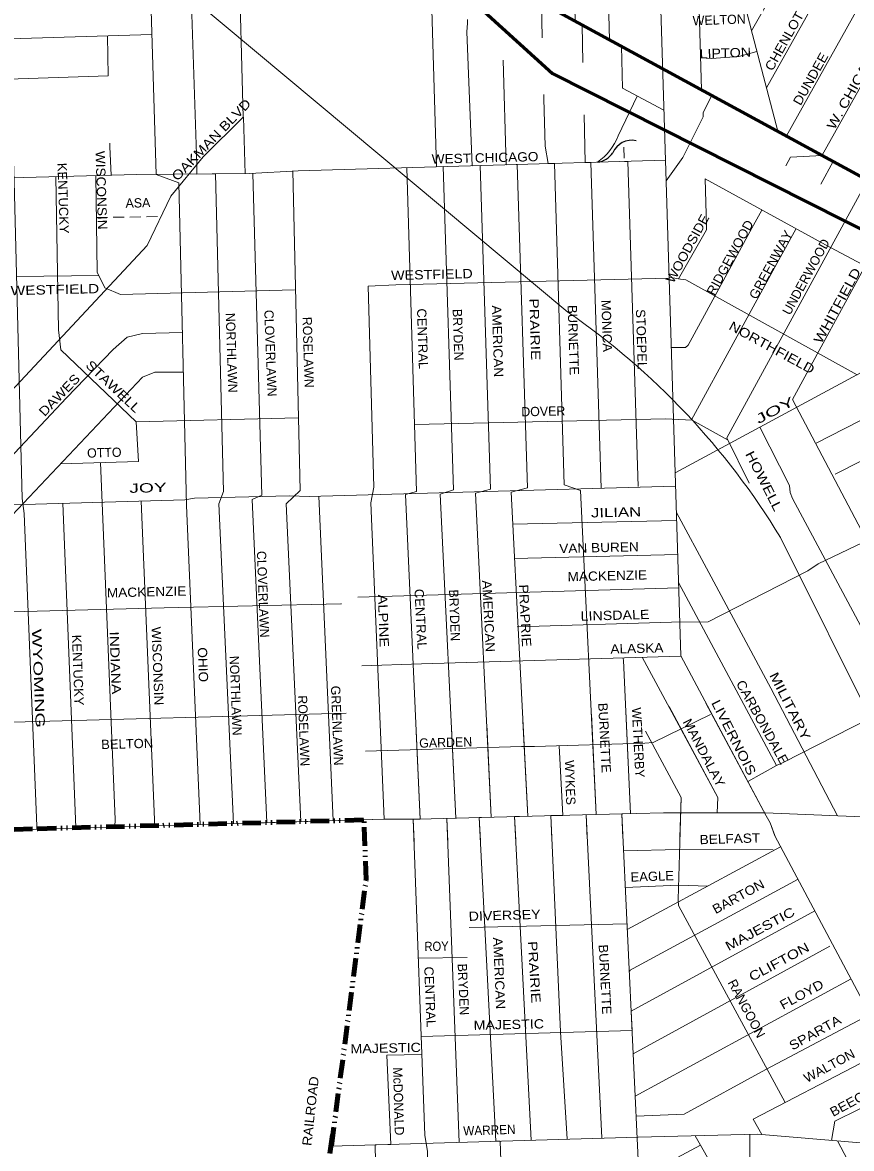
# Model space of a CAD drawing. Extents: x 34705 to 138605, y 34275 to 143551.
# Drawn here: x 69930 to 76640, y 104782 to 113900 of the extents above; entities that cross this region are included whole.
import ezdxf
from ezdxf.enums import TextEntityAlignment as Align

# ---------------------------------------------------------------- set-up
doc = ezdxf.new("R2010")
doc.units = 0
doc.header["$LTSCALE"] = 30
for name, pattern in [('DASH_DOUBLE_DOT', [9.2, 5, -1.2, 0.3, -1.2, 0.3, -1.2]), ('DOT_DASHED', [7.7, 5, -1.2, 0.3, -1.2]), ('MEDIUM_DASHED', [4.5, 3, -1.5])]:
    doc.linetypes.add(name, pattern=pattern)
for name, color, linetype, lineweight in [('1', 7, 'Continuous', 13), ('11', 7, 'Continuous', 13), ('50', 7, 'Continuous', 13), ('51', 7, 'Continuous', 35), ('59', 7, 'DASH_DOUBLE_DOT', 106), ('60', 7, 'DOT_DASHED', 53)]:
    doc.layers.add(name, color=color, linetype=linetype, lineweight=lineweight)

msp = doc.modelspace()

# ---------------------------------------------------------------- linework, layer by layer
at = {"layer": '1'}
for p, q in [((76370.24, 114795.07), (75831.64, 113831.95)), ((75391.97, 114512.52), (75425.28, 113355.5)), ((76555.08, 114450.42), (75951.76, 113371.56)), ((76740.73, 114104.26), (76113.76, 112983.11)), ((70617.43, 113793.01), (70624.07, 113468.82)), ((74459.36, 113881.03), (74466.51, 113576.32)), ((76926.52, 113762.56), (76402.76, 112825.98)), ((68198.79, 113383.83), (70624.07, 113468.82)), ((74786.25, 113368.69), (75121.96, 113191.05)), ((76146.49, 112809.43), (76109.1, 112740.69)), ((76146.48, 112809.43), (76402.86, 112823.63)), ((76492.67, 112774.76), (76391.53, 112592.22)), ((69881.81, 111844.22), (70547.58, 111851.79)), ((70850.18, 110667.27), (72163.98, 110698.75)), ((70238.85, 110327.48), (70869.46, 110345.25)), ((72329.11, 110064.7), (72445.16, 107436.92)), ((73896.88, 109837.35), (75224.74, 109868.79)), ((73909.63, 109560.51), (75235.97, 109591.36)), ((75240.35, 109364.06), (76034.22, 107883.99)), ((72643.13, 109245.76), (75241.63, 109322.66)), ((73133.65, 106322.55), (73529.14, 106328.36)), ((74890, 105206), (76636.31, 106155.14)), ((72879.68, 105537.26), (73160.67, 105543.8)), ((72425.7, 104800.68), (74914.4, 104874.31)), ((76526.27, 104843.04), (78087.16, 101937.59))]:
    msp.add_line(p, q, dxfattribs=at)
at = {"layer": '1', "linetype": 'MEDIUM_DASHED'}
for p, q in [((74798.02, 112891.87), (74802.23, 112774.72)), ((70527.85, 112320.72), (71051.38, 112329.31))]:
    msp.add_line(p, q, dxfattribs=at)
at = {"layer": '1'}
for points in [[(74269.09, 141753.87), (74342.79, 139035.88), (74401.15, 136407.9), (74440.05, 135250.17), (74447.86, 135168.57), (74511.2, 133233.12), (74537.31, 132174.65), (74629.7, 129069.96), (74724.29, 126046.91), (75258.72, 108770.25), (75949.8, 107475.21), (75982.05, 107419.91), (76018.21, 107315.9)], [(69007.73, 141603.79), (69213.36, 133836.32), (69216.36, 133697.32), (69320.96, 131186.42), (69315.06, 131084.72), (69664.86, 119741.72), (69733.56, 116534.02), (69862.73, 112612.85), (69926.46, 110045.02), (69944.36, 109925.32), (70046.06, 107393.42), (70046.8, 107365.77)], [(73963.22, 121799.31), (73977.56, 121108.62), (74019.46, 120917.12), (74038.81, 120074.64), (74156.29, 116248.13), (74346.34, 116254.05), (74402.54, 113911.95), (74130.71, 114059.85), (74137.61, 113774.76)], [(73665.68, 121624.44), (73686.58, 120680.84), (73794.29, 117405.74), (73740.38, 117310.04), (73016.88, 116538.44), (72380.08, 116493.54), (72302.29, 116457.64), (72230.58, 116373.94), (72164.79, 116206.44), (71877.79, 115380.94), (71883.79, 115225.44), (71734.29, 114728.94), (71686.49, 114597.34), (71680.49, 114459.74), (71715.21, 113134.29), (71393.49, 112811.74), (71130.38, 112494.74), (70938.99, 112093.94), (69267.68, 110303.64)], [(71001.32, 119176.38), (71084.96, 115786.32), (70917.56, 115768.32), (71012.35, 112670.01), (71196.73, 112600.89), (71256.86, 109989.92), (71368.68, 107404.98)], [(71298.63, 119171.5), (71363.06, 115636.72), (71410.86, 115529.02), (71363.06, 115385.52), (71348.06, 115289.82), (71382.46, 114167.72), (71297.26, 114045.62), (71340.66, 112750.52), (71341.04, 112672.83), (71493.34, 112674.05), (71555.86, 110103.62), (71519.96, 110001.92), (71638.19, 107412.98)], [(75405.77, 115619.67), (75410.76, 115425.13), (75452.23, 115314.52), (75475.26, 115222.35), (75839.23, 113802.88), (76043.09, 113021.53)], [(74639.92, 115277.12), (74682.58, 113759.59), (74778.51, 113707.39), (74786.25, 113368.69)], [(73226.83, 114551.62), (73281.44, 112731.37), (73334.08, 112732.87), (73418.56, 110115.52), (73310.86, 110079.72), (73437.44, 107457.03), (73364.47, 107455.1), (73371.61, 107269.17)], [(73533.05, 113925.62), (73532.16, 113896.02), (73527.66, 113825.72), (73569.44, 112739.58), (73634.13, 112741.42), (73717.46, 110120.02), (73597.86, 110090.12), (73724.19, 107464.57), (73627.46, 107462.03), (73637.15, 107273.85)], [(67208.17, 113613.36), (68168.67, 113645.13), (68268.59, 113652.81), (69826.91, 113700.01), (69824.71, 113766.8), (70977.7, 113803.41)], [(75417.85, 113613.75), (75505.9, 113608.86), (75728.5, 113624.39), (75875.08, 113665.45)], [(73820.39, 113595.61), (73845.4, 112747.44), (73933.44, 112749.95), (74016.46, 110132.02), (73884.96, 110096.12), (74020.19, 107472.36), (73912.95, 107469.54), (73922.73, 107278.9)], [(74148.72, 113315.89), (74149.56, 113281.42), (74161.46, 112898.62), (74185.08, 112757.13), (74236.21, 112758.58), (74315.46, 110157.42), (74446.96, 110109.62), (74574.11, 107486.97), (74491.36, 107484.77), (74501.01, 107289.11)], [(75510.26, 113309.27), (75438.4, 113171.5), (75439.91, 113136.64)], [(74476.44, 113153.12), (74485.52, 112765.69), (74529.83, 112766.95), (74615.17, 110129.51)], [(70635.63, 112923.81), (70636.56, 112894.12), (70648.64, 112663.29)], [(54478.94, 112274.29), (54716.56, 112260.76), (55127.41, 112276.57), (57617.68, 112322.7), (58701.41, 112345.76), (60793.93, 112407.27), (61762.37, 112422.65), (68207.1, 112599.49), (70854.93, 112668.68), (71769.57, 112676.37), (72161.56, 112699.44), (75134.56, 112784.19)], [(73041.6, 112724.52), (73119.56, 110102.12), (73029.86, 110078.22), (73148.37, 107449.42), (73093.02, 107449.07), (73099.68, 107264.36)], [(74802.28, 112774.72), (74829.47, 112775.51), (74913.46, 110144.02)], [(70199.8, 112651.56), (70222.46, 111410.62), (70240.99, 111249.53), (70850.26, 110665.92), (70869.46, 110345.25)], [(70522.5, 112659.99), (70534.86, 111877.22), (70597.72, 111751.51)], [(71794.92, 112677.86), (71866.86, 110073.72), (71789.06, 110037.82), (71907.46, 107420.97)], [(72117.23, 112698.17), (72177.76, 110109.62), (72064.16, 110001.92), (72181.93, 107429.11)], [(75455.17, 112634.83), (75466.05, 112249.77), (75466.05, 112222.12), (75240.45, 111823.6)], [(75455.17, 112634.83), (76428.94, 112098.84), (77530.06, 111513.54), (78101.34, 111195.54), (78156.63, 111144.85), (78838.49, 110762.33), (79271.56, 109937.38), (79294.6, 109886.69), (79379.38, 109747.16), (80363.34, 107847.51), (80366.86, 107839.75)], [(76769.59, 112624.1), (75631.9, 110537.66), (75811.58, 110168.97)], [(75913.59, 112381.17), (75834.62, 112235.95), (75318.62, 111286.56), (75295.58, 111268.13), (75181.46, 111268.13)], [(76189.56, 112227.67), (76051.16, 111977.86), (75346.07, 110682.48)], [(76792.46, 112003.16), (76161.73, 110846.44), (77940.09, 107470.6), (77986.16, 107360), (77991.01, 107350.74)], [(72727.44, 111766.22), (72953.22, 111774.9), (75164.09, 111829.61)], [(75163.87, 111836.73), (75255.78, 111821.41), (75298.05, 111815.37), (76685.65, 111048.29)], [(70597.72, 111751.51), (70724.27, 111698.02), (72130.81, 111736.46)], [(72727.44, 111766.22), (72774.26, 110136.22), (72750.26, 110010.62), (72857.01, 107449.07)], [(75212.85, 110253.29), (77129.23, 111287.72), (77365.61, 111722.71)], [(76348.66, 110491.59), (77304.3, 110978.94), (77631.51, 111584.89)], [(76507.27, 110241.55), (77553.09, 110771.55), (77919.49, 111458.06)], [(69465.46, 109983.99), (69655.91, 110191.07), (70286.16, 110859.97), (70662.78, 111252.08), (70778.07, 111352.03), (70901.05, 111382.79), (71224.55, 111390.88)], [(67367.97, 107285.64), (70901.05, 111029.12), (71000.97, 111067.56), (71232.01, 111067.56)], [(73935.18, 109006.07), (75183.97, 109043.02), (75480.77, 109047.66), (76287.71, 109460.53), (76371.18, 109516.2), (76793.2, 109720.32), (77340.43, 109984.75), (79025.46, 110855.54)], [(73103.44, 110644.27), (75134.03, 110689.67), (75351.33, 110679.56), (75641.26, 110518.44)], [(75897.88, 110623.06), (76138.69, 110150.53), (76143.3, 110095.23), (76161.73, 110044.53), (77000.23, 108482.2), (77601.54, 107343.86)], [(70562.04, 110336.58), (70681.36, 107447.22), (70677.87, 107388.21)], [(68637.52, 109960.41), (71243.21, 110034.61), (71322.05, 110048.53), (72091.88, 110067.09), (72249.56, 110062.45), (75216.15, 110146.55)], [(75800.37, 107755.23), (76032.64, 107883.25), (76088.29, 107906.45), (77901.58, 108834.26), (77961.87, 108862.09), (80403.28, 110131.97)], [(70256.72, 110006.52), (70362.96, 107381.42), (70363.01, 107379.45)], [(70889.69, 110024.55), (70998.26, 107447.22), (70999.57, 107397.15)], [(75222.8, 109931.53), (75484.48, 109445.41), (75986.66, 108509.85), (76526.88, 107477.14)], [(74914.4, 104874.31), (75879.58, 104897.58), (77259.02, 104781.25), (77456.7, 104757.99), (78323.04, 104711.46), (84801.63, 104845.23), (85092.35, 104868.5), (85377.25, 104932.47), (86652.03, 105479.2), (88419.59, 106217.85), (88564.94, 106305.1), (90681.35, 107194.97), (91332.56, 107474.15), (91408.14, 107549.76), (94615.68, 108918.91), (95226.7, 109227.44), (95367, 109272.3)], [(68602.92, 109145.43), (68710.53, 109114.67), (69325.41, 109114.67), (71077.83, 109160.8), (72507.43, 109191.56), (72512.09, 109193.6)], [(71799.82, 107417.78), (72854.4, 107449.07), (73135.18, 107449.07), (74461.98, 107483.99), (75119.56, 107501.46), (75940.09, 107501.46), (76923.55, 107460.71), (79190.16, 107396.67), (79463.67, 107390.85), (82223.48, 108790.85), (82415.51, 108802.49)], [(72676.52, 108691.8), (73160.74, 108707.18), (75258.94, 108769.83)], [(74791.71, 108750.7), (74793.86, 108733.72), (74850.29, 107494.31), (74780.41, 107492.45), (74789.91, 107294.21)], [(74946.87, 108760.51), (75559.16, 107625.62), (75551.5, 107501.46)], [(74812.44, 108325.57), (74850.29, 107494.31), (74780.41, 107492.45), (74920.1, 104577.53)], [(74812.44, 108325.57), (74850.29, 107494.31), (74780.41, 107492.45), (74789.91, 107294.21)], [(75162.96, 108359.98), (75559.16, 107625.62), (75551.5, 107501.46)], [(75461.99, 108389.33), (75949.8, 107475.21), (75982.05, 107419.91), (76018.91, 107313.91), (77396.45, 104728.46), (77433.31, 104686.98), (77737.38, 104216.9), (82924.91, 94574.55), (82977.39, 94535.18), (83082.34, 94397.38), (83174.18, 94325.2), (83252.9, 94239.89), (83370.97, 94092.26), (86141.27, 88934.48)], [(75461.99, 108389.33), (75949.8, 107475.21), (75982.05, 107419.91), (76018.21, 107315.9)], [(64054.86, 108068.52), (65609.22, 108115.16), (66247.16, 108138.23), (66800.56, 108161.29), (69751.99, 108230.49), (72549.8, 108306.86)], [(72707.27, 107999.83), (73967.78, 108038.28), (74075.38, 108038.28), (74966, 108064.17), (75035.56, 108068.81), (75499.32, 108296.13)], [(73980.42, 108243.9), (74020.19, 107472.36), (73912.95, 107469.54), (74047.51, 104848.66)], [(73980.42, 108243.9), (74020.19, 107472.36), (73912.95, 107469.54), (73922.73, 107278.9)], [(74534.77, 108298.32), (74574.11, 107486.97), (74491.36, 107484.77), (74620.46, 104868.02)], [(74534.77, 108298.32), (74574.11, 107486.97), (74491.36, 107484.77), (74501.01, 107289.11)], [(73116.37, 108159.09), (73148.37, 107449.42), (73093.02, 107449.07), (73185.36, 104889.02), (73209.26, 104757.42), (73209.26, 104530.12), (73257.06, 104320.72), (73298.78, 103540.43)], [(73116.37, 108159.09), (73148.37, 107449.42), (73093.02, 107449.07), (73099.68, 107264.36)], [(73402.2, 108187.15), (73437.44, 107457.03), (73364.47, 107455.1), (73465.23, 104831.43)], [(73402.2, 108187.15), (73437.44, 107457.03), (73364.47, 107455.1), (73371.61, 107269.17)], [(73688.07, 108215.21), (73724.19, 107464.57), (73627.46, 107462.03), (73762.57, 104840.23), (73795.46, 104841.2), (73831.06, 103818.22), (75570.7, 100585.06)], [(73688.07, 108215.21), (73724.19, 107464.57), (73627.46, 107462.03), (73637.15, 107273.85)], [(74972.32, 108160.83), (75260.26, 107625.62), (75237.47, 106799.48), (75240.82, 106749.31), (76103.36, 105155.22)], [(74972.32, 108160.83), (75260.26, 107625.62), (75251.34, 107302.36)], [(74272.82, 108044.02), (74302.65, 107479.8), (74206.82, 107477.27), (74285.56, 105726.42), (74338.38, 104857.27)], [(74272.82, 108044.02), (74302.65, 107479.8), (74206.82, 107477.27), (74215.5, 107284.07)], [(67367.31, 107286.26), (72854.4, 107449.07), (73135.18, 107449.07), (74461.98, 107483.99), (75119.56, 107501.46), (75940.09, 107501.46), (76923.55, 107460.71), (79190.16, 107396.67), (79463.67, 107390.85), (80510.1, 107913.93)], [(73546.58, 106572.64), (74823.15, 106601.95), (74825.42, 106554.46), (76064.18, 107224.05)], [(74794.91, 107191.65), (75246.41, 107203.31), (76006.04, 107200.79)], [(74848.99, 106217.85), (74843.17, 106223.67), (74843.17, 106223.67), (76209.54, 106962.32)], [(74809.06, 106896.04), (75241.14, 106913.81), (75477.72, 106907.05)], [(73157.02, 105688.58), (74864.61, 105736.28), (74857.11, 105892.77), (76343.27, 106706.41)], [(74873.57, 105549.16), (76465.37, 106421.42), (76465.37, 106421.42)], [(74897.81, 105042.82), (75285.06, 105060.43), (75947.89, 105421.03), (76789.15, 105868.28)], [(72879.68, 105537.26), (72911.4, 104815.04), (72785.5, 104811.32), (72799.66, 103982.12), (72727.86, 103916.32), (72680.06, 103240.32), (72715.96, 103222.32), (73092.66, 102486.52), (73092.66, 102414.72), (74248.1, 100280.95)], [(75914.7, 104894.62), (75843.24, 105019.72), (76715.38, 105473.38), (76949.06, 105568.14)], [(76478.69, 104847.06), (76506.07, 105002.27), (76506.07, 105002.27), (77095.16, 105293.93)], [(75375.48, 104885.43), (76647.46, 102649.52), (76701.26, 102529.92), (78212.65, 99865.66)], [(75817.86, 104896.09), (75817.86, 104679.02), (75817.86, 104679.02), (75991.64, 104385.29)], [(72453.55, 103926.08), (73854.74, 103972.8), (75418.52, 104809.78)]]:
    msp.add_lwpolyline(points, dxfattribs=at)
at = {"layer": '1', "lineweight": 53}
msp.add_lwpolyline([(35051.57, 135383.85), (35124.2, 135323.83), (40544.24, 132389.75), (44352.38, 130313.49), (48721.15, 127927.26), (52359.24, 125955.06), (53781.74, 125169.15), (55156.63, 124418.97), (56043.46, 123936.71), (56442.24, 123716.41), (57585, 123085.31), (70109.98, 116247.42), (80624.23, 110526.89), (82336.58, 109591.28)], dxfattribs=at)
at = {"layer": '1', "lineweight": 25}
for centre, radius, start, end in [((74860.26, 112781.5), 164.96, 76.86865, 157.36667), ((74559.05, 112947.55), 180.86, 278.13826, 325.44953)]:
    msp.add_arc(centre, radius, start, end, dxfattribs=at)
at = {"layer": '11'}
for p, q in [((74751.96, 112981.52), (74904.85, 113304.67)), ((71717.54, 113134.97), (71731.48, 112673.53)), ((75439.91, 113136.64), (75275.91, 112806.08)), ((75139.65, 112619.34), (75275.91, 112806.08))]:
    msp.add_line(p, q, dxfattribs=at)
msp.add_arc((74308.14, 113157.92), 477.59, 305.37836, 338.3249, dxfattribs=at)
at = {"layer": '50'}
for p, q in [((74343.99, 111555.68), (68327.72, 116584.25)), ((77255.06, 107337.75), (76064.72, 109730.08))]:
    msp.add_line(p, q, dxfattribs=at)
msp.add_arc((70934.45, 106618.27), 6000.24, 31.23926, 55.37289, dxfattribs=at)
at = {"layer": '51', "lineweight": 60}
msp.add_lwpolyline([(67942.15, 119618.13), (70194.46, 119620.82), (71080.59, 119480.93), (71991.18, 119251.97), (72371.35, 118958.42), (72513.07, 118739.92), (72699.81, 118466.38), (72873.22, 118232.88), (72986.6, 117952.66), (73093.32, 117545.69), (73133.33, 116251.38), (73093.32, 116131.29), (73053.3, 115824.39), (73073.31, 115577.54), (73140, 115243.96), (73300.07, 114723.56), (73666.9, 113989.68), (74218.8, 113487.65), (77177.29, 111994.8), (78236.88, 111462.14), (80168.01, 110411.99), (80456.46, 110276.91), (82330.6, 109176.08), (82543.51, 108967.12)], dxfattribs=at)
at = {"layer": '59'}
for p, q in [((72687.9, 107442.97), (70046.94, 107371.07)), ((72711.02, 106958.36), (72693.9, 107443.1)), ((67378.71, 107296.26), (70050.62, 107371.79)), ((72431.46, 104804.94), (72711.02, 106958.36)), ((72437.92, 104891.45), (72261.09, 103577.27))]:
    msp.add_line(p, q, dxfattribs=at)
at = {"layer": '60'}
msp.add_line((72693.9, 107443.1), (72687.9, 107442.97), dxfattribs=at)

# ---------------------------------------------------------------- texts
at = {"layer": '11'}
for s, rotation, width, p in [('CHENLOT', 60.689, 1.1, (76129.12, 113731.37)), ('W. CHICAGO', 60.688, 1.25, (76690.79, 113362.83)), ('LIPTON', 1.999, 1.15, (75620.08, 113615.91)), ('DUNDEE', 60.689, 1.1, (76341.9, 113425.04)), ('OAKMAN BLVD', 46.076, 1.2, (71484.84, 112924.46)), ('WISCONSIN', 271.816, 1.1, (70531.3, 112540.81)), ('WEST CHICAGO', 1.371, 1.1, (73674.79, 112767.44)), ('KENTUCKY', 271.816, 1.05, (70222.01, 112476.19)), ('WOODSIDE', 61.379, 1.1, (75345.56, 112051.73)), ('RIDGEWOOD', 61.378, 1.05, (75690.03, 111978.7)), ('GREENWAY', 61.379, 1.05, (76019.54, 111920.93)), ('WESTFIELD', 1.371, 1.15, (73244.75, 111822.41)), ('WHITFIELD', 61.377, 1.25, (76557.63, 111589.69)), ('WESTFIELD ', 1.373, 1.25, (70210.65, 111700.44)), ('AMERICAN', 271.84, 1.1, (73738.67, 111318.09)), ('PRAIRIE', 271.839, 1.25, (74039.88, 111413.81)), ('BURNETTE', 271.839, 1.05, (74351.37, 111327.81)), ('MONICA', 271.837, 1.05, (74622.1, 111442.33)), ('CENTRAL', 271.839, 1.05, (73130.99, 111337.77)), ('STOEPEL', 271.838, 1.05, (74902.68, 111334.5)), ('NORTHFIELD', 331.377, 1.2, (75977.9, 111234.92)), ('STAWELL', 316.777, 1.2, (70639.27, 110925.21)), ('DAWES', 46.075, 1.15, (70255.77, 110857)), ('JOY', 28.219, 1.75, (76036.76, 110727.47)), ('HOWELL ', 296.865, 1.25, (75905.59, 110154.35)), ('JOY', 1.539, 1.55, (70946.79, 110094.79)), ('JILIAN', 1.356, 1.35, (74735.44, 109896.63)), ('VAN BUREN', 1.385, 1.1, (74597.12, 109610.42)), ('MACKENZIE', 1.392, 1.1, (74664.43, 109382.41)), ('MACKENZIE', 1.392, 1.1, (70935.25, 109251.97)), ('AMERICAN', 272.999, 1.1, (73665.46, 109091.03)), ('PRAPRIE', 273.002, 1.15, (73960.67, 109094.98)), ('ALPINE', 272.003, 1.2, (72814.24, 109053.78)), ('CENTRAL', 273.001, 1.05, (73115.11, 109066.67)), ('LINSDALE', 1.489, 1.15, (74727.02, 109062.85)), ('WYOMING', 272.206, 1.6, (70022.02, 108587.57)), ('WISCONSIN', 272.205, 1.1, (70986.43, 108687.98)), ('KENTUCKY', 272.205, 1.05, (70340.97, 108654.54)), ('INDIANA', 272.207, 1.25, (70644.03, 108713.52)), ('ALASKA', 1.561, 1.1, (74904.08, 108794.57)), ('OHIO', 272.203, 1.1, (71353.45, 108698.18)), ('MILITARY', 296.865, 1.3, (76109.07, 108346.39)), ('CARBONDALE', 298.865, 1.1, (75886.29, 108215.75)), ('LIVERNOIS', 296.866, 1.25, (75653.98, 108093.57)), ('BURNETTE', 273.001, 1.05, (74604.22, 108105.41)), ('MANDALAY', 297.743, 1.1, (75412.9, 107968.79)), ('BELTON', 1.472, 1.05, (70778.26, 108021.51)), ('BELFAST', 1.711, 1.1, (75657.03, 107253.04)), ('EAGLE', 2.064, 1.05, (75028.43, 106948.76)), ('BARTON', 28.677, 1.1, (75742.01, 106789.39)), ('DIVERSEY', 1.681, 1.15, (73833.75, 106633.39)), ('MAJESTIC', 28.408, 1.25, (75917.19, 106527.37)), ('ROY', 1.303, 0.9, (73282.34, 106382.32)), ('AMERICAN', 272.461, 1.1, (73751.44, 106199.71)), ('PRAIRIE', 273.46, 1.25, (74035.08, 106208.62)), ('BURNETTE', 273.001, 1.05, (74608.12, 106148.76)), ('CLIFTON', 28.416, 1.25, (76071.02, 106260.27)), ('CENTRAL', 272.459, 1.05, (73191.44, 106008.34)), ('FLOYD', 28.448, 1.15, (76254.55, 105996.03)), ('MAJESTIC', 1.303, 1.15, (73867.22, 105748.44)), ('SPARTA', 29.264, 1.15, (76363.32, 105687.11)), ('MAJESTIC', 1.303, 1.15, (72870.31, 105557.57)), ('WALTON', 28.253, 1.05, (76477.67, 105418.41)), ('RAILROAD', 83.743, 1.1, (72298.45, 105080.94)), ('BEECHTON', 28.252, 1.1, (76761.09, 105182.31)), ('WARREN', 1.873, 0.95, (73710.11, 104893.98))]:
    msp.add_text(s, height=75, rotation=rotation, dxfattribs=dict(at, width=width)).set_placement(p, align=Align.CENTER)
for s, rotation, p in [('WELTON', 2, (75570.59, 113884.63)), ('ASA', 1.675, (70865.3, 112402.17)), ('UNDERWOOD', 61.379, (76305.26, 111823.11)), ('NORTHLAWN', 271.815, (71585.14, 111224.57)), ('CLOVERLAWN', 272.207, (71900.3, 111220.87)), ('BRYDEN', 271.841, (73418.57, 111370.59)), ('ROSELAWN', 271.816, (72205.38, 111228.63)), ('DOVER', 1.371, (74146.3, 110714.35)), ('OTTO', 1.675, (70593.33, 110379.83)), ('CLOVERLAWN', 272.207, (71840.05, 109268.78)), ('BRYDEN', 272.001, (73389.85, 109098.51)), ('NORTHLAWN', 272.206, (71618.34, 108447.45)), ('GREENLAWN', 272.207, (72439.02, 108205.09)), ('ROSELAWN', 272.206, (72169.31, 108163.34)), ('WETHERBY', 273.002, (74876.43, 108067.5)), ('GARDEN', 1.563, (73356.39, 108032.94)), ('WYKES', 271.999, (74325.41, 107744.27)), ('BRYDEN', 272.462, (73461.38, 106068.72)), ('RANGOON', 298.061, (75757.69, 105897.61)), ('McDONALD', 271.555, (72936.53, 105162.89))]:
    msp.add_text(s, height=75, rotation=rotation, dxfattribs=at).set_placement(p, align=Align.CENTER)

doc.saveas('drawing.dxf')
